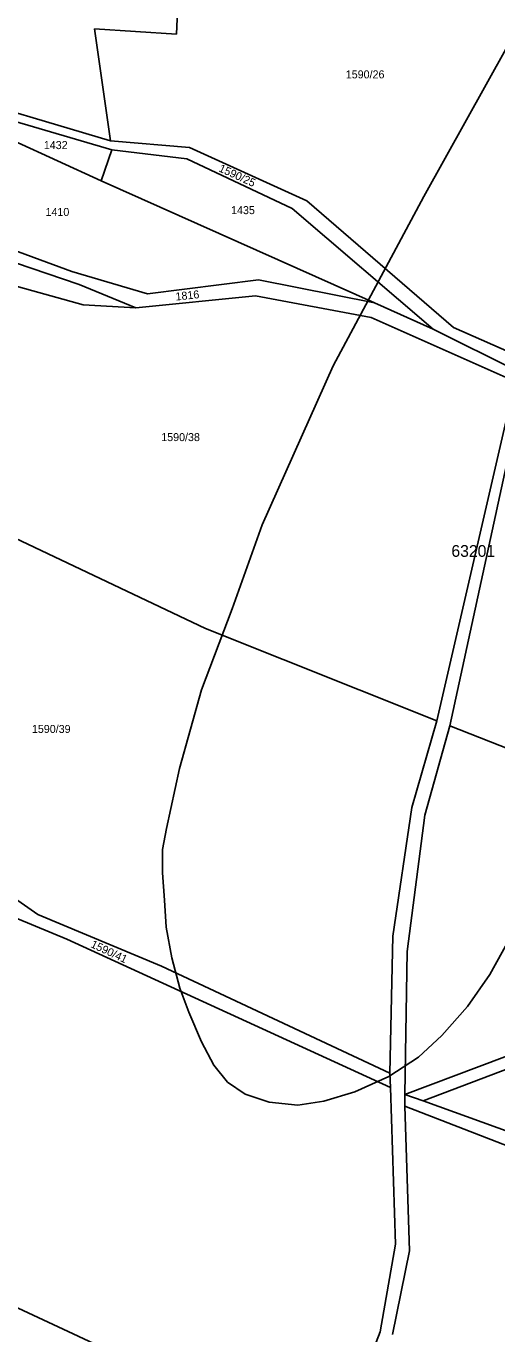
# Model space of a CAD drawing. Extents: x -546762 to -540209, y -1046851 to -1035694.
# Drawn here: x -543406.7 to -543306.6, y -1041296.2 to -1041018.4 of the extents above; entities that cross this region are included whole.
import ezdxf

# ---------------------------------------------------------------- set-up
doc = ezdxf.new("R2010")
doc.units = 0
for name, color, linetype in [('Vrstva 1', 7, 'Continuous'), ('Vrstva 18', 7, 'Continuous'), ('Vrstva 52', 7, 'Continuous'), ('Vrstva 53', 7, 'Continuous'), ('Vrstva 6', 7, 'Continuous')]:
    doc.layers.add(name, color=color, linetype=linetype)

msp = doc.modelspace()

# ---------------------------------------------------------------- linework, layer by layer
at = {"layer": 'Vrstva 1'}
msp.add_lwpolyline([(-543431.95, -1041279.74), (-543383.75, -1041302.19)], dxfattribs=at)
at = {"layer": 'Vrstva 52'}
msp.add_lwpolyline([(-543299.54, -1041204.34), (-543308.14, -1041219.86), (-543312.86, -1041226.64), (-543318.31, -1041232.82), (-543323.27, -1041237.43), (-543329.57, -1041241.54), (-543336.84, -1041244.82), (-543343.38, -1041246.76), (-543348.95, -1041247.6), (-543355, -1041247), (-543360.09, -1041245.3), (-543363.85, -1041242.76), (-543366.75, -1041239.12), (-543369.42, -1041234.15), (-543372.08, -1041227.85), (-543374.02, -1041222.76), (-543375.71, -1041216.34), (-543376.92, -1041209.8), (-543377.29, -1041204.1), (-543377.65, -1041198.29), (-543377.65, -1041193.32), (-543376.83, -1041188.83), (-543374.08, -1041176.1), (-543369.42, -1041159.35), (-543362.85, -1041142.18), (-543356.49, -1041124.36), (-543341.44, -1041090.54), (-543322.15, -1041054.55), (-543304.35, -1041022.63)], dxfattribs=at)
at = {"layer": 'Vrstva 6'}
for points in [[(-543374.73, -1041020.11), (-543372.85, -1040977.28)], [(-543392.14, -1041018.95), (-543388.72, -1041042.77)], [(-543392.14, -1041018.95), (-543374.73, -1041020.11)], [(-543425.02, -1041031.98), (-543388.72, -1041042.77)], [(-543425.91, -1041033.68), (-543388.46, -1041044.69)], [(-543390.74, -1041051.26), (-543418.63, -1041038.5)], [(-543388.72, -1041042.77), (-543371.95, -1041044.16)], [(-543388.46, -1041044.69), (-543390.74, -1041051.26)], [(-543388.46, -1041044.69), (-543372.52, -1041046.55)], [(-543371.95, -1041044.16), (-543347.04, -1041055.52)], [(-543372.52, -1041046.55), (-543350.1, -1041057.12)], [(-543390.74, -1041051.26), (-543332.62, -1041077.18)], [(-543347.04, -1041055.52), (-543315.88, -1041082.44)], [(-543431.81, -1041057.67), (-543396.93, -1041070.5)], [(-543350.1, -1041057.12), (-543320.16, -1041082.74)], [(-543432.7, -1041060.57), (-543395.4, -1041073.26)], [(-543432.81, -1041066.97), (-543394.55, -1041077.61)], [(-543396.93, -1041070.5), (-543380.89, -1041075.28)], [(-543395.4, -1041073.26), (-543383.34, -1041078.21)], [(-543380.89, -1041075.28), (-543357.28, -1041072.26)], [(-543357.28, -1041072.26), (-543332.62, -1041077.18)], [(-543383.34, -1041078.21), (-543357.93, -1041075.65)], [(-543357.93, -1041075.65), (-543333.32, -1041080.3)], [(-543394.55, -1041077.61), (-543383.34, -1041078.21)], [(-543332.62, -1041077.18), (-543320.16, -1041082.74)], [(-543333.32, -1041080.3), (-543302.74, -1041093.86)], [(-543320.16, -1041082.74), (-543302.24, -1041091.7)], [(-543315.88, -1041082.44), (-543301.55, -1041088.72)], [(-543302.74, -1041093.86), (-543319.4, -1041166)], [(-543300.97, -1041094.95), (-543316.64, -1041167.03)], [(-543438.46, -1041113.18), (-543368.51, -1041146.37)], [(-543368.51, -1041146.37), (-543319.4, -1041166)], [(-543319.4, -1041166), (-543324.68, -1041184.37)], [(-543316.64, -1041167.03), (-543321.91, -1041185.99)], [(-543282.45, -1041180.49), (-543316.64, -1041167.03)], [(-543324.68, -1041184.37), (-543328.75, -1041211.68)], [(-543321.91, -1041185.99), (-543325.72, -1041214.94)], [(-543415.11, -1041199.52), (-543404.18, -1041207.1)], [(-543398.04, -1041212.36), (-543408.39, -1041208.02)], [(-543404.18, -1041207.1), (-543377.9, -1041218.12)], [(-543398.04, -1041212.36), (-543329.26, -1041243.87)], [(-543329.36, -1041240.81), (-543328.75, -1041211.68)], [(-543325.72, -1041214.94), (-543326.16, -1041245.33)], [(-543377.9, -1041218.12), (-543329.36, -1041240.81)], [(-543252.09, -1041217.48), (-543326.16, -1041245.33)], [(-543253.04, -1041220.4), (-543322.31, -1041246.71)], [(-543329.26, -1041243.87), (-543329.36, -1041240.81)], [(-543328.2, -1041277.15), (-543329.26, -1041243.87)], [(-543326.2, -1041247.85), (-543326.16, -1041245.33)], [(-543322.31, -1041246.71), (-543326.16, -1041245.33)], [(-543249.28, -1041277.66), (-543326.2, -1041247.85)], [(-543325.21, -1041278.57), (-543326.2, -1041247.85)], [(-543322.31, -1041246.71), (-543236.3, -1041277.76)], [(-543328.2, -1041277.15), (-543331.43, -1041295.8)], [(-543328.81, -1041296.37), (-543325.21, -1041278.57)], [(-543341.28, -1041321.16), (-543331.43, -1041295.8)]]:
    msp.add_lwpolyline(points, dxfattribs=at)

# ---------------------------------------------------------------- texts
at = {"layer": 'Vrstva 18'}
for s, p in [('1590/26', (-543338.74, -1041029.48)), ('1432', (-543402.9, -1041044.5)), ('1410', (-543402.54, -1041058.71)), ('1435', (-543363.11, -1041058.32)), ('1590/38', (-543377.95, -1041106.54)), ('1590/39', (-543405.43, -1041168.54))]:
    msp.add_text(s, height=1.7, dxfattribs=at).set_placement(p)
for s, rotation, p in [('1590/25', 335.4881, (-543365.88, -1041049.18)), ('1816', 6.0183, (-543374.82, -1041076.69)), ('1590/41', 334.8218, (-543393.09, -1041214))]:
    msp.add_text(s, height=1.7, rotation=rotation, dxfattribs=at).set_placement(p)
at = {"layer": 'Vrstva 53'}
msp.add_text('63201', height=2.5, dxfattribs=at).set_placement((-543316.3, -1041131.13))

doc.saveas('drawing.dxf')
